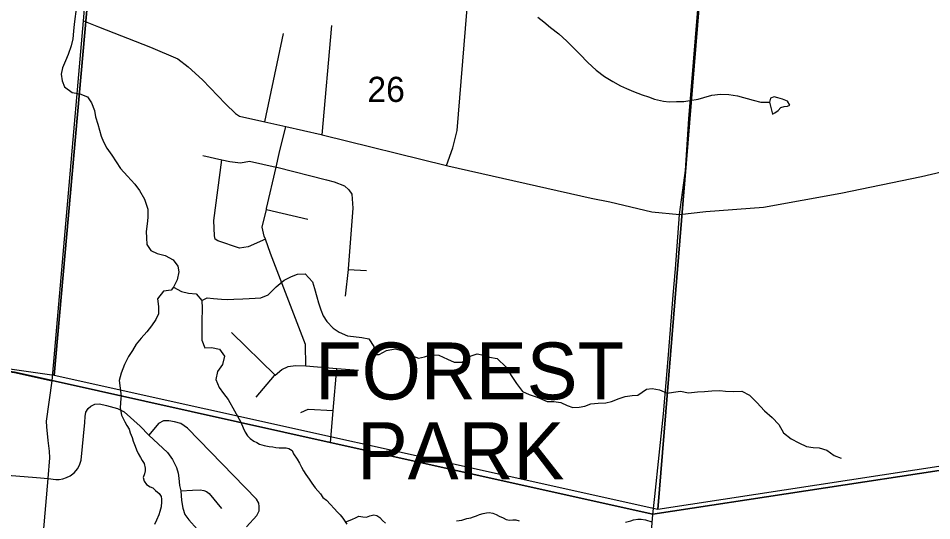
# Model space of a CAD drawing. Extents: x 0 to 34, y 0 to 22.
# Drawn here: x 10.816 to 12.335, y 15.142 to 15.978 of the extents above; entities that cross this region are included whole.
import ezdxf

# ---------------------------------------------------------------- set-up
doc = ezdxf.new("R2010")
doc.units = 0
for name, color, linetype in [('GM_X_City_Street', 7, 'Continuous'), ('GM_X_Corporation_Text', 7, 'Continuous'), ('GM_X_County_Road', 7, 'Continuous'), ('GM_X_Minor_River', 7, 'Continuous'), ('GM_X_Section', 7, 'Continuous'), ('GM_X_Section_Text', 7, 'Continuous'), ('GM_X_Township_Road', 7, 'Continuous'), ('SC_Scratch1', 7, 'Continuous'), ('SH_Cut_Line', 7, 'Continuous')]:
    doc.layers.add(name, color=color, linetype=linetype)

msp = doc.modelspace()

# ---------------------------------------------------------------- linework, layer by layer
at = {"layer": 'GM_X_City_Street'}
for p, q in [((10.8724, 15.3746), (10.9243, 15.9735)), ((11.3215, 15.7838), (11.3373, 15.9658)), ((11.2259, 15.8054), (11.2571, 15.9525)), ((11.2285, 15.6593), (11.2975, 15.6432)), ((11.3644, 15.5595), (11.3948, 15.5582)), ((11.2433, 15.3841), (11.1705, 15.4549))]:
    msp.add_line(p, q, dxfattribs=at)
for points in [[(11.5278, 15.7325), (11.5385, 15.7623), (11.5455, 15.791), (11.562, 15.9879), (11.5878, 16.2492), (11.591, 16.281)], [(11.2941, 15.3994), (11.2933, 15.4351), (11.2351, 15.5866), (11.2268, 15.6099), (11.225, 15.6149), (11.2215, 15.6302), (11.2285, 15.6593), (11.2289, 15.6609), (11.2447, 15.7299), (11.25, 15.7528), (11.2608, 15.7975)], [(11.123, 15.7494), (11.1544, 15.7422), (11.1675, 15.7391), (11.1853, 15.7373), (11.2005, 15.74), (11.2447, 15.7299), (11.2457, 15.7297), (11.3285, 15.7087), (11.3411, 15.7055), (11.3584, 15.6987), (11.3655, 15.6921), (11.3707, 15.6848), (11.3722, 15.662), (11.3646, 15.5607), (11.3644, 15.5595), (11.3596, 15.5156)], [(11.2268, 15.6099), (11.1985, 15.5972), (11.1841, 15.5952), (11.148, 15.6073), (11.1435, 15.6104), (11.1421, 15.6157), (11.1414, 15.6412), (11.1544, 15.7422)], [(11.2113, 15.3473), (11.2423, 15.3832), (11.2433, 15.3841), (11.2542, 15.3933), (11.2649, 15.3984), (11.2767, 15.4001), (11.2941, 15.3994), (11.3459, 15.3953), (11.3815, 15.3924)], [(11.3349, 15.2713), (11.3397, 15.3252), (11.3459, 15.3953)], [(11.2858, 15.3216), (11.298, 15.3275), (11.3397, 15.3252)]]:
    msp.add_lwpolyline(points, dxfattribs=at)
at = {"layer": 'GM_X_County_Road'}
msp.add_line((10.9243, 15.9735), (10.9323, 16.0643), dxfattribs=at)
for points in [[(10.7588, 15.3957), (10.8099, 15.3885), (10.8724, 15.3746)], [(10.8236, 14.7192), (10.844, 14.9628), (10.8472, 15.0003), (10.8655, 15.2119), (10.8685, 15.2466), (10.8681, 15.2573), (10.8659, 15.2752), (10.8632, 15.2981), (10.8628, 15.3076), (10.8724, 15.3746)], [(11.8596, 15.0231), (11.86, 15.0272), (11.8659, 15.0903), (11.8712, 15.1522)]]:
    msp.add_lwpolyline(points, dxfattribs=at)
at = {"layer": 'GM_X_Minor_River'}
for points in [[(10.9127, 15.9979), (10.9089, 15.9675), (10.9078, 15.9561), (10.9067, 15.9436), (10.9037, 15.9315), (10.8991, 15.9172), (10.8943, 15.9066), (10.8894, 15.8954), (10.8872, 15.8844), (10.8888, 15.8737), (10.8927, 15.8633), (10.9058, 15.8542), (10.9186, 15.8519), (10.931, 15.8467), (10.9376, 15.837), (10.9426, 15.8239), (10.9446, 15.8139), (10.9484, 15.8013), (10.9508, 15.7917), (10.9536, 15.7817), (10.9579, 15.7721), (10.9633, 15.7613), (10.9717, 15.75), (10.979, 15.7388), (10.986, 15.7279), (10.9974, 15.7151), (11.0099, 15.7014), (11.0173, 15.6913), (11.026, 15.6766), (11.0312, 15.6601), (11.0316, 15.646), (11.0302, 15.6358), (11.0287, 15.6229), (11.0292, 15.6126), (11.03, 15.6015), (11.0366, 15.5915), (11.0471, 15.5862), (11.0603, 15.5828), (11.0738, 15.576), (11.0811, 15.5655), (11.0831, 15.5559), (11.0801, 15.5427), (11.0741, 15.5303), (11.0872, 15.5231), (11.0989, 15.5201), (11.1118, 15.519), (11.1214, 15.5081), (11.1218, 15.4955), (11.1212, 15.4735), (11.1213, 15.4639), (11.121, 15.4529), (11.1211, 15.4419), (11.126, 15.4296), (11.1371, 15.43), (11.1503, 15.4274), (11.1587, 15.4157), (11.1553, 15.4017), (11.147, 15.3898), (11.1447, 15.3765), (11.1501, 15.3634), (11.157, 15.3534), (11.1651, 15.3436), (11.1863, 15.3058)], [(11.68, 15.9794), (11.6897, 15.9716), (11.7012, 15.9621), (11.7149, 15.9515), (11.7279, 15.9397), (11.7376, 15.9303), (11.7498, 15.9178), (11.7631, 15.9041), (11.7768, 15.8912), (11.7906, 15.8809), (11.8044, 15.8722), (11.8175, 15.8654), (11.8276, 15.8605), (11.8389, 15.8556), (11.8536, 15.8503), (11.8638, 15.847), (11.8739, 15.8433), (11.8886, 15.8398), (11.8985, 15.8388), (11.9107, 15.8389), (11.9228, 15.8393), (11.9324, 15.8406), (11.9465, 15.8432), (11.9561, 15.8456), (11.9691, 15.8495), (11.9836, 15.8513), (11.9976, 15.851), (12.012, 15.8487), (12.0377, 15.8411), (12.0505, 15.8381)], [(12.099, 15.833), (12.095, 15.8396), (12.0867, 15.8429), (12.0788, 15.8454), (12.0728, 15.847), (12.0667, 15.8449), (12.0653, 15.8381)], [(12.0505, 15.8381), (12.0653, 15.8381)], [(12.0653, 15.8381), (12.0701, 15.8182), (12.074, 15.8204), (12.0794, 15.8244), (12.0837, 15.8289), (12.0895, 15.831), (12.0952, 15.8312), (12.099, 15.833)], [(11.1214, 15.5081), (11.1302, 15.5124), (11.1404, 15.5114), (11.1541, 15.5106), (11.1644, 15.51), (11.1746, 15.5101), (11.1895, 15.5112), (11.1997, 15.5117), (11.21, 15.5118), (11.2195, 15.5127), (11.2315, 15.5177), (11.2447, 15.531), (11.2583, 15.5421), (11.2703, 15.5482), (11.2803, 15.5518), (11.2928, 15.5526), (11.305, 15.5393), (11.3085, 15.5282), (11.3123, 15.514), (11.3151, 15.5044), (11.3193, 15.4925), (11.3232, 15.4828), (11.3291, 15.4732), (11.3398, 15.4622), (11.3495, 15.4555), (11.3634, 15.4494), (11.3732, 15.448), (11.3872, 15.4465), (11.399, 15.4446), (11.4074, 15.4318), (11.4055, 15.4182), (11.4161, 15.4183), (11.4281, 15.4252), (11.4426, 15.4279), (11.4562, 15.4244), (11.4697, 15.4168), (11.4817, 15.4123), (11.4913, 15.4144), (11.5016, 15.4179), (11.5153, 15.4175), (11.5296, 15.4107), (11.5408, 15.4058), (11.5541, 15.4058), (11.5673, 15.4153), (11.5788, 15.4192), (11.5894, 15.4174), (11.5996, 15.4141), (11.6124, 15.4115), (11.6273, 15.397), (11.6356, 15.3834), (11.6444, 15.3699), (11.6543, 15.3567), (11.6655, 15.3518), (11.6787, 15.3476), (11.6952, 15.3399), (11.7067, 15.34), (11.718, 15.3386), (11.7285, 15.3333), (11.7383, 15.3304), (11.7486, 15.3309), (11.7581, 15.3325), (11.7681, 15.3361), (11.7803, 15.3373), (11.7929, 15.3377), (11.8024, 15.3401), (11.8151, 15.3451), (11.8251, 15.3486), (11.8365, 15.3502), (11.8464, 15.3507), (11.8604, 15.3606), (11.8699, 15.3619), (11.882, 15.3593), (11.8952, 15.354), (11.9055, 15.3556), (11.9169, 15.3576), (11.9305, 15.3545), (11.9454, 15.356), (11.9568, 15.3569), (11.9694, 15.358), (11.9823, 15.3585), (11.9922, 15.3574), (12.0047, 15.3567), (12.0192, 15.3571), (12.0319, 15.3506), (12.0441, 15.3385), (12.057, 15.3245), (12.0697, 15.3135), (12.0808, 15.3017), (12.0884, 15.2878), (12.1014, 15.2783), (12.1138, 15.2715), (12.1269, 15.2655), (12.1379, 15.2637), (12.1477, 15.263), (12.1605, 15.2592), (12.1725, 15.2505), (12.1841, 15.246)], [(11.0741, 15.5303), (11.0701, 15.5255), (11.0575, 15.5239), (11.0473, 15.5112), (11.0489, 15.4982), (11.0489, 15.4861), (11.0448, 15.4763), (11.0373, 15.4658), (11.0295, 15.4561), (11.0201, 15.4457), (11.0122, 15.4353), (11.0058, 15.4248), (10.9995, 15.4151), (10.9926, 15.4019), (10.9873, 15.3872), (10.9839, 15.3752), (10.9869, 15.3493)], [(10.9869, 15.3493), (10.9867, 15.3456), (10.9856, 15.3296), (10.9863, 15.3235), (10.9877, 15.3174), (10.9902, 15.3121), (10.9931, 15.3063), (10.9964, 15.3005), (11.0001, 15.294), (11.0023, 15.2879), (11.0051, 15.2802), (11.0069, 15.2741), (11.0102, 15.2656), (11.0127, 15.2599), (11.0156, 15.2534), (11.0193, 15.2472), (11.0218, 15.2422), (11.0251, 15.2368), (11.0269, 15.2295), (11.0268, 15.2246), (11.0256, 15.2197), (11.0239, 15.2136), (11.0253, 15.2075), (11.029, 15.2021), (11.0354, 15.1982), (11.0399, 15.1966), (11.0444, 15.1919), (11.05, 15.1869), (11.0533, 15.1822), (11.054, 15.1776), (11.0542, 15.1731), (11.0533, 15.1647), (11.0516, 15.1572), (11.0496, 15.1519), (11.046, 15.1428), (11.0425, 15.1353)], [(11.1863, 15.3058), (11.19, 15.2966), (11.1932, 15.2894), (11.1973, 15.2828), (11.2017, 15.2785), (11.2077, 15.2742), (11.2126, 15.2718), (11.2171, 15.2691), (11.225, 15.267), (11.233, 15.2654), (11.239, 15.2645), (11.2443, 15.2636), (11.2496, 15.2631), (11.2614, 15.2629), (11.2659, 15.262), (11.2712, 15.2589), (11.2737, 15.2531), (11.2796, 15.2443), (11.2837, 15.2377), (11.287, 15.2312), (11.2903, 15.225), (11.2943, 15.2185), (11.2995, 15.2111), (11.3043, 15.2046), (11.3098, 15.1965), (11.3183, 15.1864), (11.3224, 15.1806), (11.3284, 15.176), (11.3351, 15.1686), (11.3414, 15.162), (11.3466, 15.1562), (11.351, 15.1515), (11.3555, 15.1461), (11.3621, 15.1361)], [(11.3598, 15.1396), (11.3718, 15.1447), (11.3768, 15.1468), (11.3825, 15.1494), (11.3889, 15.1481), (11.395, 15.148), (11.4003, 15.1498), (11.4072, 15.1516), (11.4121, 15.1507), (11.417, 15.1472), (11.4215, 15.1425), (11.4267, 15.1379)], [(11.5444, 15.1416), (11.5536, 15.1429), (11.562, 15.1454), (11.5685, 15.1468), (11.573, 15.1486), (11.578, 15.15), (11.583, 15.1522), (11.5891, 15.1536), (11.5944, 15.155), (11.599, 15.1553), (11.605, 15.1544), (11.6107, 15.152), (11.6156, 15.1497), (11.6224, 15.1469), (11.6272, 15.1441), (11.6329, 15.1428), (11.6386, 15.1431), (11.6432, 15.1434), (11.6488, 15.1418)], [(11.8257, 15.1394), (11.8345, 15.1419), (11.839, 15.1433), (11.8463, 15.1443), (11.8516, 15.1446), (11.8592, 15.1436), (11.8693, 15.14)]]:
    msp.add_lwpolyline(points, dxfattribs=at)
at = {"layer": 'GM_X_Section'}
for points in [[(9.8925, 16.5517), (10.9657, 16.3888), (10.8757, 15.3833), (9.8158, 15.534)], [(10.9657, 16.3888), (11.9608, 16.1562), (11.8797, 15.1603), (10.8757, 15.3833)], [(11.9608, 16.1562), (12.9642, 16.3503), (12.8901, 15.3152), (11.8797, 15.1603)]]:
    msp.add_lwpolyline(points, close=True, dxfattribs=at)
at = {"layer": 'GM_X_Township_Road'}
for p, q in [((11.9086, 15.5609), (11.9156, 15.6511)), ((11.8964, 15.4113), (11.9022, 15.481)), ((11.8931, 15.3715), (11.8964, 15.4113)), ((11.8712, 15.1522), (11.8743, 15.1821))]:
    msp.add_line(p, q, dxfattribs=at)
for points in [[(11.9156, 15.6511), (11.9252, 15.7242), (11.9312, 15.8105), (11.9607, 16.1743)], [(10.9243, 15.9735), (10.9493, 15.9631), (11.0356, 15.9293), (11.0815, 15.9101), (11.0987, 15.8968), (11.1225, 15.875), (11.1608, 15.8355), (11.1772, 15.8191), (11.184, 15.8148), (11.2259, 15.8054), (11.2608, 15.7975), (11.3197, 15.7842), (11.3215, 15.7838), (11.5278, 15.7325), (11.5302, 15.7319), (11.7685, 15.6786), (11.7997, 15.6724), (11.8697, 15.6559), (11.9156, 15.6511), (11.9593, 15.6562), (12.0551, 15.6633), (12.184, 15.6868), (12.3178, 15.7142), (12.3509, 15.7223)], [(11.9022, 15.481), (11.9052, 15.5168), (11.9086, 15.5609)], [(11.8743, 15.1821), (11.8888, 15.3198), (11.8931, 15.3715)], [(10.8655, 15.2119), (10.8784, 15.2107), (10.8838, 15.2107), (10.8903, 15.2113), (10.8964, 15.2135), (10.9023, 15.2164), (10.9087, 15.2217), (10.9148, 15.2286), (10.9181, 15.2358), (10.9208, 15.2427), (10.9264, 15.3055), (10.9271, 15.3151), (10.9285, 15.3223), (10.9323, 15.3287), (10.9368, 15.3324), (10.943, 15.3355), (10.9509, 15.3361), (10.9629, 15.3335), (10.981, 15.3286), (10.9919, 15.3231), (11.0185, 15.2992), (11.0328, 15.2839), (11.0639, 15.2553), (11.0724, 15.2437), (11.0791, 15.2304), (11.0818, 15.221), (11.0827, 15.2125), (11.0841, 15.2002), (11.086, 15.1916), (11.0873, 15.1754), (11.0896, 15.1628), (11.0927, 15.1524), (11.0996, 15.1435), (11.1134, 15.1277)], [(11.1952, 15.1315), (11.2124, 15.1503), (11.2165, 15.1582), (11.2167, 15.1654), (11.2157, 15.1708), (11.2121, 15.1777), (11.0975, 15.2959), (11.0864, 15.3035), (11.0755, 15.3062), (11.0661, 15.3082), (11.0576, 15.3081), (11.049, 15.3036), (11.0328, 15.2839)], [(10.6658, 15.2312), (10.7218, 15.2239), (10.8462, 15.2139), (10.8655, 15.2119)], [(11.086, 15.1916), (11.1059, 15.1928), (11.1182, 15.1935), (11.1246, 15.1923), (11.1288, 15.1902), (11.1333, 15.1873), (11.154, 15.162)]]:
    msp.add_lwpolyline(points, dxfattribs=at)
at = {"layer": 'SC_Scratch1'}
for points in [[(9.3, 19.6321), (9.3, 15.5386), (9.3203, 15.5382), (9.4956, 15.5344), (9.7079, 15.5298), (9.8057, 15.5286), (9.8186, 15.5274), (9.8466, 15.5235), (9.8971, 15.5164), (9.9322, 15.5115), (10.0263, 15.4984), (10.3999, 15.4462), (10.7586, 15.3962), (10.8097, 15.389), (10.8722, 15.3751), (11.3346, 15.2718), (11.871, 15.1527), (12.8889, 15.308)], [(12.8889, 15.308), (11.871, 15.1527), (11.3346, 15.2718), (10.8722, 15.3751), (10.8097, 15.389), (10.7586, 15.3962), (10.3999, 15.4462), (10.0263, 15.4984), (9.9322, 15.5115), (9.8971, 15.5164), (9.8466, 15.5235), (9.8186, 15.5274), (9.7681, 14.9604), (9.6983, 14.1431), (9.6977, 14.1364), (9.6954, 14.0973), (9.6771, 13.958)]]:
    msp.add_lwpolyline(points, dxfattribs=at)
at = {"layer": 'SH_Cut_Line'}
for points in [[(9.3, 20.2361), (9.3, 15.5386), (9.3203, 15.5382), (9.4956, 15.5344), (9.7079, 15.5298), (9.8057, 15.5286), (9.8186, 15.5274), (9.8466, 15.5235), (9.8971, 15.5164), (9.9322, 15.5115), (10.0263, 15.4984), (10.3999, 15.4462), (10.7586, 15.3962), (10.8097, 15.389), (10.8722, 15.3751), (11.3346, 15.2718), (11.871, 15.1527), (12.8889, 15.308)], [(12.8889, 15.308), (11.871, 15.1527), (11.3346, 15.2718), (10.8722, 15.3751), (10.8097, 15.389), (10.7586, 15.3962), (10.3999, 15.4462), (10.0263, 15.4984), (9.9322, 15.5115), (9.8971, 15.5164), (9.8466, 15.5235), (9.8186, 15.5274), (9.8057, 15.5286), (9.7079, 15.5298), (9.4956, 15.5344), (9.3203, 15.5382), (9.3, 15.5386), (9.3, 13.4361), (16.1, 13.4361)]]:
    msp.add_lwpolyline(points, dxfattribs=at)

# ---------------------------------------------------------------- texts
at = {"layer": 'GM_X_Corporation_Text'}
for s, p in [('FOREST', (11.3096, 15.3436)), ('PARK', (11.3791, 15.2109))]:
    msp.add_text(s, height=0.0947, rotation=0, dxfattribs=at).set_placement(p)
at = {"layer": 'GM_X_Section_Text'}
msp.add_text('26', height=0.04186, rotation=0, dxfattribs=at).set_placement((11.3965, 15.8384))

doc.saveas('drawing.dxf')
